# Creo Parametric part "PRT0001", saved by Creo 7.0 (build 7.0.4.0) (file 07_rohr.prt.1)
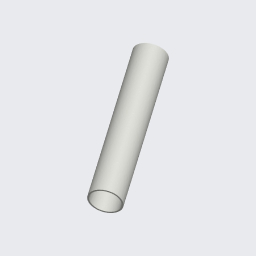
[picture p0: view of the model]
Units: millimeter Kilogram Sec (mmKs); MM, KILOGRAM, SECS
Materials in the file: S235JRG2

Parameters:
  PTC_MATERIAL_NAME = "S235JRG2"
  BENENNUNG = "XXX"
  DATUM = "XX.XX.XX"
  ERSTELLER = "ARINDA"
  TEILETYP = "Fertigungsteil"
  SELECT_EN_NAME = "S235JRG2"
  SELECT_DIN_NAME = "RSt37-2"
  SELECT_DIN_NUMBER = "1.0038"
  SELECT_ASTM_NAME = "A 283 M Grade 2"
  MATERIAL_GROUP = "ME_ST_Baustahl"
  STANDARD_EN_DELIVERYSPEC = "DIN EN 10025"
  STANDARD_DIN_DELIVERYSPEC = "DIN 17100"

Other parameters: MASSE

Created from: ARINDA-STARTTEIL.PRT

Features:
  1. coordinate system "CS0"
  2. datum plane "DTM1", "T_RECHTS_Y-Z"
  3. datum plane "DTM2", "T_OBEN_X-Z"
  4. datum plane "DTM3", "T_VORNE_X-Y"
  5. datum axis "T_X-ACHSE"
  6. datum axis "A_1"
  7. datum axis "A_2"
  8. extrusion "Profil 1"

Other named items: T_BASIC, T_Y-ACHSE, T_Z-ACHSE, COMB0001, ANNOT_LAYER_STATE0001

Layers: 00_STD-ACHSEN, 00_STD-EBENEN, 00_STD-KOORDSYS, VOLUMENGEOMETRIE

Surfaces: 2 plane, 2 cylinder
